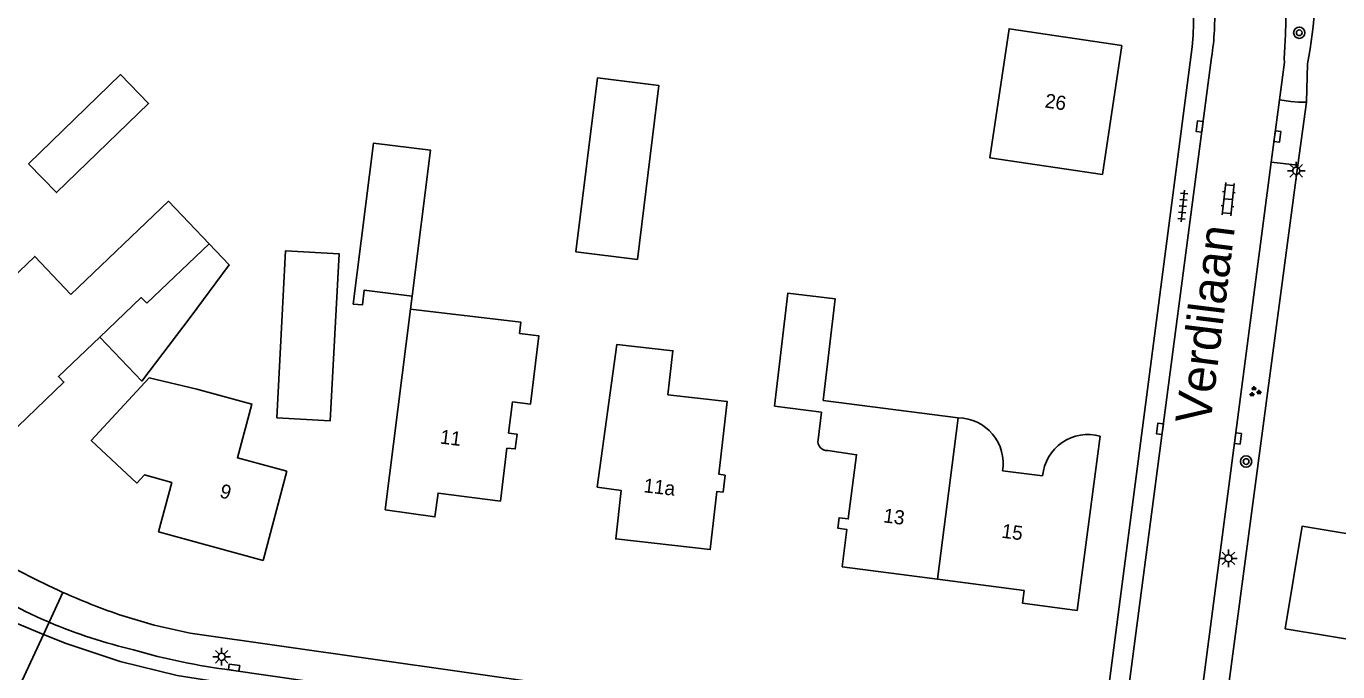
# Model space of a CAD drawing. Extents: x 136000 to 138005, y 398500 to 400500.
# Drawn here: x 137759.2 to 137852, y 398930.5 to 398976.2 of the extents above; entities that cross this region are included whole.
import ezdxf

# ---------------------------------------------------------------- set-up
doc = ezdxf.new("R2010")
doc.units = 0
for name, color, linetype in [('gg-afsc-erfafscheiding', 7, 'Continuous'), ('gg-anno-huisnummerreeks BGT', 7, 'Continuous'), ('gg-anno-openbare ruimte label', 7, 'Continuous'), ('gg-bbg-bijgebouw', 7, 'Continuous'), ('gg-bbg-gedigitaliseerde bebouwing', 7, 'Continuous'), ('gg-bbg-gedigitaliseerde bijgebouw', 7, 'Continuous'), ('gg-bbg-hoofdgebouw', 7, 'Continuous'), ('gg-bbg-luifel en loopbrug', 7, 'Continuous'), ('gg-bbg-tussenscheiding', 7, 'Continuous'), ('gg-knt-verharding', 7, 'Continuous'), ('gg-knt-verharding nz', 7, 'Continuous'), ('gt-grn-groengrens', 7, 'Continuous'), ('gt-grn-vlakafsluiter', 7, 'Continuous'), ('gt-grn-weggrens', 7, 'Continuous'), ('gt-symb-boom', 7, 'Continuous'), ('gt-symb-groenvak', 7, 'Continuous'), ('gt-symb-klinker verharding', 7, 'Continuous'), ('gt-symb-kolk', 7, 'Continuous'), ('gt-symb-lichtmast', 7, 'Continuous'), ('gt-symb-tegel verharding', 7, 'Continuous')]:
    doc.layers.add(name, color=color, linetype=linetype)

# ---------------------------------------------------------------- blocks, each defined once
blk = doc.blocks.new('gt0-KOLK')
at = {"layer": 'gt-symb-kolk'}
blk.add_lwpolyline([(0, 0), (0.375, 0), (0.375, 0.4), (-0.375, 0.4), (-0.375, 0), (0, 0)], dxfattribs=at)
blk = doc.blocks.new('gt0-BOOM')
at = {"layer": 'gt-symb-boom'}
for radius in [0.4, 0.2]:
    blk.add_circle((0, 0), radius, dxfattribs=at)
blk = doc.blocks.new('gt0-KL1')
at = {"layer": 'gt-symb-klinker verharding'}
for p, q in [((-1.15, 0.3), (1.15, 0.3)), ((-1, -0.3), (-1, 0.3)), ((-0.5, 0.3), (-0.5, 0.45)), ((0, -0.3), (0, 0.3)), ((0.5, 0.3), (0.5, 0.45)), ((1, -0.3), (1, 0.3)), ((-1.15, -0.3), (1.15, -0.3)), ((-0.5, -0.45), (-0.5, -0.3)), ((0.5, -0.45), (0.5, -0.3))]:
    blk.add_line(p, q, dxfattribs=at)
blk = doc.blocks.new('gt0-LMAST')
at = {"layer": 'gt-symb-lichtmast'}
for p, q in [((-0.182, 0.173), (-0.447, 0.438)), ((-0.005, 0.246), (-0.005, 0.621)), ((0.172, 0.173), (0.437, 0.438)), ((-0.255, -0.004), (-0.63, -0.004)), ((-0.182, -0.181), (-0.447, -0.446)), ((-0.005, -0.254), (-0.005, -0.629)), ((0.437, -0.446), (0.172, -0.181)), ((0.245, -0.004), (0.62, -0.004))]:
    blk.add_line(p, q, dxfattribs=at)
blk.add_circle((-0.005, -0.004), 0.25, dxfattribs=at)
blk = doc.blocks.new('gt0-GRVAK')
at = {"layer": 'gt-symb-groenvak'}
for p, q in [((-0.11, 0.189), (-0.228, 0.24)), ((-0.182, 0.153), (0.088, 0.153)), ((-0.091, 0.211), (-0.156, 0.322)), ((-0.047, 0.214), (-0.047, 0.393)), ((-0.004, 0.211), (0.061, 0.322)), ((0.015, 0.189), (0.133, 0.24)), ((0.262, -0.052), (0.197, 0.059)), ((0.305, -0.049), (0.305, 0.13)), ((0.349, -0.052), (0.414, 0.059)), ((-0.245, -0.228), (-0.363, -0.177)), ((-0.318, -0.264), (-0.047, -0.264)), ((-0.226, -0.206), (-0.291, -0.095)), ((-0.183, -0.203), (-0.183, -0.024)), ((-0.139, -0.206), (-0.074, -0.095)), ((-0.12, -0.228), (-0.002, -0.177)), ((0.243, -0.074), (0.125, -0.023)), ((0.17, -0.11), (0.441, -0.11)), ((0.368, -0.074), (0.486, -0.023))]:
    blk.add_line(p, q, dxfattribs=at)
blk = doc.blocks.new('gt0-TEG1')
at = {"layer": 'gt-symb-tegel verharding'}
for p, q in [((-1.125, 0), (1.125, 0)), ((-0.9, -0.25), (-0.9, 0.25)), ((-0.45, -0.25), (-0.45, 0.25)), ((0, -0.25), (0, 0.25)), ((0.45, -0.25), (0.45, 0.25)), ((0.9, -0.25), (0.9, 0.25))]:
    blk.add_line(p, q, dxfattribs=at)

msp = doc.modelspace()

# ---------------------------------------------------------------- linework, layer by layer
at = {"layer": 'gg-afsc-erfafscheiding'}
for p, q in [((137849.172, 398966.355), (137843.585, 398924.323)), ((137786.524, 398957.085), (137786.402, 398956.179))]:
    msp.add_line(p, q, dxfattribs=at)
at = {"layer": 'gg-bbg-bijgebouw'}
msp.add_lwpolyline([(137786.524, 398957.085), (137783.112, 398957.513), (137783.002, 398956.483), (137782.35, 398956.534)], dxfattribs=at)
at = {"layer": 'gg-bbg-gedigitaliseerde bebouwing'}
for p, q in [((137767.739, 398956.599), (137772.148, 398960.789)), ((137767.904, 398951.303), (137771.29, 398950.505)), ((137828.27, 398944.716), (137831.11, 398944.37))]:
    msp.add_line(p, q, dxfattribs=at)
for points in [[(137836.71, 398974.82), (137828.739, 398976.012), (137827.369, 398966.884), (137835.34, 398965.69)], [(137762.378, 398957.217), (137769.268, 398963.802), (137772.148, 398960.789)], [(137756.515, 398956.759), (137759.808, 398959.906), (137762.378, 398957.217)], [(137825.147, 398948.482), (137815.59, 398949.706), (137816.435, 398956.906), (137813.076, 398957.301), (137812.138, 398949.312)], [(137793.604, 398949.608), (137794.889, 398949.453), (137795.47, 398954.285), (137794.11, 398954.449), (137794.206, 398955.24), (137786.402, 398956.179)], [(137799.59, 398943.58), (137800.997, 398953.675), (137804.959, 398953.225), (137804.604, 398950.107), (137808.796, 398949.631), (137808.208, 398944.48), (137808.65, 398944.43)], [(137771.29, 398950.505), (137775.178, 398949.449), (137774.146, 398945.649), (137777.657, 398944.696)], [(137793.604, 398949.608), (137793.338, 398947.394), (137793.95, 398947.32)]]:
    msp.add_lwpolyline(points, dxfattribs=at)
for centre, start, end in [((137825.085, 398945.252), 350.44339, 88.89185), ((137834.326, 398944.071), 74.70836, 174.69513)]:
    msp.add_arc(centre, 3.23, start, end, dxfattribs=at)
at = {"layer": 'gg-bbg-gedigitaliseerde bijgebouw'}
for points in [[(137759.363, 398966.465), (137761.342, 398964.417), (137767.861, 398970.719), (137765.882, 398972.767), (137759.363, 398966.465)], [(137798.09, 398960.234), (137802.444, 398959.693), (137803.972, 398971.991), (137799.618, 398972.532), (137798.09, 398960.234)], [(137782.35, 398956.534), (137783.779, 398967.929), (137787.821, 398967.422), (137786.524, 398957.085)], [(137776.927, 398948.478), (137780.72, 398948.277), (137781.347, 398960.096), (137777.554, 398960.298), (137776.927, 398948.478)]]:
    msp.add_lwpolyline(points, dxfattribs=at)
at = {"layer": 'gg-bbg-hoofdgebouw'}
for p, q in [((137836.71, 398974.82), (137835.34, 398965.69)), ((137784.607, 398941.96), (137786.402, 398956.179)), ((137775.964, 398938.392), (137777.657, 398944.696)), ((137775.964, 398938.392), (137768.57, 398940.4)), ((137816.93, 398937.934), (137823.683, 398937.053)), ((137823.683, 398937.053), (137829.811, 398936.253))]:
    msp.add_line(p, q, dxfattribs=at)
for points in [[(137767.739, 398956.599), (137767.35, 398956.985), (137764.422, 398954.199)], [(137764.422, 398954.199), (137761.493, 398951.412), (137761.882, 398951.003), (137757.291, 398946.619)], [(137768.57, 398940.4), (137769.506, 398943.909), (137767.575, 398944.449), (137767.04, 398943.864), (137763.813, 398946.875), (137767.904, 398951.303)], [(137815.231, 398946.922), (137815.459, 398948.875), (137812.138, 398949.312)], [(137784.607, 398941.96), (137788.12, 398941.47), (137788.34, 398943.15), (137792.76, 398942.59), (137793.21, 398946.33), (137793.81, 398946.28), (137793.95, 398947.32)], [(137835.178, 398947.187), (137833.561, 398934.853), (137829.694, 398935.36), (137829.811, 398936.253)], [(137816.93, 398937.934), (137817.266, 398940.574), (137816.626, 398940.663), (137816.713, 398941.404), (137817.361, 398941.321), (137817.945, 398945.87), (137815.91, 398946.157)], [(137808.65, 398944.43), (137808.51, 398943.22), (137808.07, 398943.27), (137807.6, 398939.15), (137800.91, 398939.91), (137801.3, 398943.33), (137799.59, 398943.58)], [(137853.98, 398932.6), (137848.27, 398933.54), (137849.46, 398940.8), (137853.44, 398940.15), (137853.56, 398940.9)]]:
    msp.add_lwpolyline(points, dxfattribs=at)
msp.add_arc((137815.867, 398946.802), 0.647, 169.339, 273.84435, dxfattribs=at)
at = {"layer": 'gg-bbg-luifel en loopbrug'}
for points in [[(137772.148, 398960.789), (137773.556, 398959.316), (137770.812, 398955.568)], [(137764.422, 398954.199), (137767.386, 398951.083), (137770.812, 398955.568)]]:
    msp.add_lwpolyline(points, dxfattribs=at)
at = {"layer": 'gg-bbg-tussenscheiding'}
for p, q in [((137824.72, 398945.148), (137825.147, 398948.482)), ((137823.683, 398937.053), (137824.72, 398945.148))]:
    msp.add_line(p, q, dxfattribs=at)
at = {"layer": 'gg-knt-verharding'}
for p, q in [((137841.7, 398974.74), (137835.09, 398924.09)), ((137847.862, 398970.975), (137847.287, 398966.575)), ((137847.287, 398966.575), (137849.172, 398966.355)), ((137773.71, 398930.63), (137829.994, 398922.515))]:
    msp.add_line(p, q, dxfattribs=at)
for points in [[(137843.06, 398973.991), (137836.74, 398925.85), (137836.54, 398924.83), (137836.267, 398924.384), (137835.948, 398923.968)], [(137847.862, 398970.975), (137848.21, 398973.644), (137848.187, 398973.888)], [(137847.862, 398970.975), (137848.67, 398970.866), (137849.215, 398970.826), (137849.767, 398970.828)], [(137847.287, 398966.575), (137842.05, 398926.49), (137842.058, 398925.511), (137842.224, 398924.546)], [(137835.09, 398924.09), (137770.818, 398933.23), (137768.26, 398933.809), (137765.748, 398934.561)]]:
    msp.add_lwpolyline(points, dxfattribs=at)
for centre, radius, start, end in [((137812.082, 398977.075), 29.71, 355.4915, 20.55756), ((137810.763, 398977.026), 37.555, 355.20641, 16.24471), ((137826.046, 398976.761), 17.238, 350.7543, 3.59658), ((137780.359, 398976.119), 46.471, 224.56963, 242.93017), ((137781.803, 398980.722), 48.874, 238.72538, 245.84895), ((137781.825, 398980.803), 48.957, 245.86395, 250.82924), ((137776.003, 398970.011), 39.065, 244.54137, 247.14725), ((137775.903, 398969.802), 38.834, 247.16417, 256.44462), ((137779.188, 398974.803), 44.512, 253.84141, 262.93017)]:
    msp.add_arc(centre, radius, start, end, dxfattribs=at)
at = {"layer": 'gg-knt-verharding nz'}
for points in [[(137706.51, 398982.273), (137715.153, 398973.739), (137726.908, 398962.216), (137735.691, 398953.556), (137742.934, 398946.343), (137748.767, 398940.74), (137751.956, 398938.077), (137755.281, 398935.713), (137758.577, 398933.921), (137760.437, 398933.154)], [(137760.437, 398933.154), (137762.029, 398932.497), (137765.853, 398931.234), (137769.893, 398930.246), (137777.66, 398929.005), (137781.797, 398928.432), (137785.807, 398927.897), (137789.779, 398927.311), (137793.827, 398926.739), (137829.855, 398921.55)]]:
    msp.add_lwpolyline(points, dxfattribs=at)
at = {"layer": 'gt-grn-groengrens'}
msp.add_line((137849.767, 398970.828), (137849.849, 398973.531), dxfattribs=at)
msp.add_arc((137821.451, 398979.195), 28.957, 348.7195, 22.44923, dxfattribs=at)
at = {"layer": 'gt-grn-vlakafsluiter'}
msp.add_line((137849.767, 398970.828), (137849.172, 398966.355), dxfattribs=at)
at = {"layer": 'gt-grn-weggrens'}
for p, q in [((137760.832, 398934.012), (137761.806, 398936.126)), ((137760.437, 398933.154), (137760.832, 398934.012)), ((137758.768, 398929.528), (137760.437, 398933.154))]:
    msp.add_line(p, q, dxfattribs=at)

# ---------------------------------------------------------------- block references
at = {"layer": 'gt-symb-boom'}
for p in [(137849.264, 398975.734), (137845.504, 398945.386)]:
    msp.add_blockref('gt0-BOOM', p, dxfattribs=at)
at = {"layer": 'gt-symb-groenvak'}
msp.add_blockref('gt0-GRVAK', (137846.111, 398950.321), dxfattribs=at)
at = {"layer": 'gt-symb-klinker verharding', "rotation": -95.96703762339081}
msp.add_blockref('gt0-KL1', (137844.24, 398963.955), dxfattribs=at)
at = {"layer": 'gt-symb-kolk'}
for p, rotation in [((137842.413, 398969.071), 82.53402593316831), ((137847.924, 398968.366), 82.53402593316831), ((137839.604, 398947.675), 82.53402593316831), ((137845.131, 398946.987), 82.53402593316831), ((137773.891, 398930.604), -8.16250946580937)]:
    msp.add_blockref('gt0-KOLK', p, dxfattribs=dict(at, rotation=rotation))
at = {"layer": 'gt-symb-lichtmast'}
for p in [(137849.055, 398965.965), (137844.261, 398938.534), (137773.038, 398931.568)]:
    msp.add_blockref('gt0-LMAST', p, dxfattribs=at)
at = {"layer": 'gt-symb-tegel verharding', "rotation": -95.96703762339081}
msp.add_blockref('gt0-TEG1', (137841.03, 398963.462), dxfattribs=at)

# ---------------------------------------------------------------- texts
at = {"layer": 'gg-anno-huisnummerreeks BGT'}
for s, rotation, p in [('26', 351.5, (137831.225, 398970.453)), ('11', 352.8, (137788.442, 398946.664)), ('9', 344.8, (137772.834, 398942.868)), ('11a', 353.5, (137802.845, 398943.213)), ('13', 352.6, (137819.806, 398941.088)), ('15', 352.6, (137828.166, 398939.997))]:
    msp.add_text(s, height=1, rotation=rotation, dxfattribs=at).set_placement(p)
at = {"layer": 'gg-anno-openbare ruimte label'}
msp.add_text('Verdilaan', height=2.5, rotation=82.9, dxfattribs=at).set_placement((137842.971, 398947.938))

doc.saveas('drawing.dxf')
